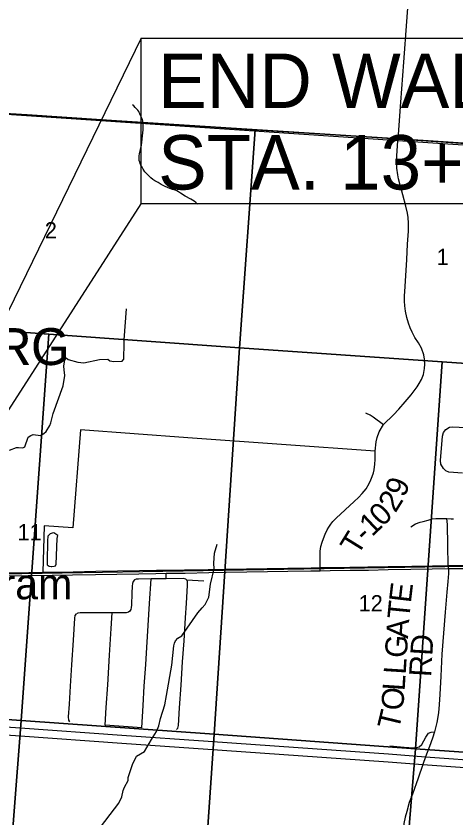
# Model space of a CAD drawing. Extents: x 0 to 34, y 0 to 22.
# Drawn here: x 3.646 to 4.778, y 16.59 to 18.654 of the extents above; entities that cross this region are included whole.
import ezdxf

# ---------------------------------------------------------------- set-up
doc = ezdxf.new("R2010")
doc.units = 0
for name, color, linetype in [('GM_X_City_Street', 7, 'Continuous'), ('GM_X_Corporation', 7, 'Continuous'), ('GM_X_Corporation_Text', 7, 'Continuous'), ('GM_X_Interstate_Route', 7, 'Continuous'), ('GM_X_Minor_Lake', 7, 'Continuous'), ('GM_X_Minor_River', 7, 'Continuous'), ('GM_X_Rail_Line', 7, 'Continuous'), ('GM_X_Section', 7, 'Continuous'), ('GM_X_Section_Text', 7, 'Continuous'), ('GM_X_Township_Road', 7, 'Continuous'), ('GM_X_Township_Road_Text', 7, 'Continuous'), ('GM_X_Unincorporated_Text', 7, 'Continuous'), ('GM_X_US_Route', 7, 'Continuous'), ('SH_Text', 7, 'Continuous')]:
    doc.layers.add(name, color=color, linetype=linetype)

msp = doc.modelspace()

# ---------------------------------------------------------------- linework, layer by layer
at = {"layer": 'GM_X_City_Street'}
for points in [[(3.4177, 18.4149), (4.6284, 18.3336), (5.2084, 18.2946), (5.2627, 18.2891), (5.912, 18.251), (6.0938, 18.2359), (6.2605, 18.224), (6.3251, 19.3282)], [(4.113, 18.1698), (4.1088, 18.1735), (4.1041, 18.1771), (4.0958, 18.1823), (4.0812, 18.1905), (4.0693, 18.1977), (4.0641, 18.2013), (4.0598, 18.2038), (4.0552, 18.2057), (4.049, 18.2077), (4.0417, 18.2102), (4.0299, 18.2154), (4.0196, 18.2205), (4.0115, 18.2252), (4.0036, 18.2298), (3.9982, 18.2332), (3.9929, 18.2372), (3.9884, 18.2413), (3.9831, 18.2467), (3.9776, 18.2531), (3.973, 18.2599), (3.9694, 18.2662), (3.9673, 18.2703), (3.9656, 18.2745), (3.9645, 18.278), (3.9632, 18.2821), (3.9627, 18.2868), (3.9627, 18.2902), (3.9629, 18.2936), (3.9635, 18.2989), (3.9686, 18.3216), (3.9728, 18.3528), (3.9733, 18.3609), (3.9736, 18.3673), (3.9735, 18.3729), (3.973, 18.3777), (3.9723, 18.3835), (3.9712, 18.3878), (3.9691, 18.393), (3.9667, 18.3978), (3.9647, 18.4021), (3.963, 18.4058), (3.9617, 18.4084), (3.9594, 18.4115), (3.9565, 18.4147), (3.9527, 18.4184), (3.9488, 18.4223), (3.9462, 18.4254)]]:
    msp.add_lwpolyline(points, dxfattribs=at)
at = {"layer": 'GM_X_Corporation'}
for points in [[(3.4218, 18.4152), (4.6285, 18.3373), (5.2113, 18.299), (5.2682, 18.2953), (5.912, 18.251), (6.0938, 18.2359), (6.2646, 18.2231), (6.3253, 19.1073), (6.3374, 19.2897), (6.3556, 19.5188), (6.3621, 19.6044), (6.385, 20.0884), (6.3883, 20.1254), (6.389, 20.1539), (6.3927, 20.2003), (6.4001, 20.2844), (6.4016, 20.3608), (6.4097, 20.4361), (6.4277, 20.7531), (6.4325, 20.8009), (6.4385, 20.9), (2.1, 20.9)], [(7.0679, 18.1923), (6.7672, 18.2007), (6.2646, 18.2231), (6.0938, 18.2359), (5.912, 18.251), (5.2682, 18.2953), (5.2113, 18.299), (4.6285, 18.3373), (3.4218, 18.4152)]]:
    msp.add_lwpolyline(points, dxfattribs=at)
at = {"layer": 'GM_X_Interstate_Route'}
for points in [[(3.3501, 16.8435), (3.6568, 16.822), (3.9185, 16.8032), (4.14, 16.7877), (4.3722, 16.7712), (4.604, 16.7548), (4.6996, 16.7473), (4.8669, 16.7351), (5.1594, 16.714), (5.3993, 16.6976), (5.5708, 16.6871), (5.7197, 16.6768), (5.8676, 16.668), (5.8733, 16.6677), (6.0223, 16.6571), (6.2793, 16.6405), (6.5008, 16.6267), (6.5803, 16.6216)], [(3.3497, 16.8226), (3.6565, 16.8011), (3.9181, 16.7823), (4.1396, 16.7667), (4.3718, 16.7503), (4.6036, 16.7339), (4.693, 16.7276), (4.8604, 16.7157), (5.1529, 16.6946), (5.3928, 16.6782), (5.5644, 16.6677), (5.7091, 16.6577), (5.7188, 16.6572), (5.8539, 16.6483)]]:
    msp.add_lwpolyline(points, dxfattribs=at)
at = {"layer": 'GM_X_Minor_Lake'}
for points in [[(3.7517, 17.3091), (3.754, 17.3167), (3.7437, 17.3236), (3.7388, 17.3232), (3.7343, 17.3213), (3.7282, 17.3153), (3.727, 17.3035), (3.727, 17.283), (3.7262, 17.2697), (3.7265, 17.2409)], [(3.7265, 17.2409), (3.7318, 17.2378), (3.7368, 17.2367), (3.7383, 17.2367), (3.744, 17.2382), (3.7477, 17.2389), (3.7493, 17.2431), (3.7517, 17.3091)]]:
    msp.add_lwpolyline(points, dxfattribs=at)
at = {"layer": 'GM_X_Minor_River'}
for points in [[(3.7181, 17.5795), (3.7235, 17.5844), (3.7329, 17.5996), (3.7356, 17.6068), (3.7421, 17.631), (3.7676, 17.7023), (3.7715, 17.7289), (3.7704, 17.7433), (3.7696, 17.7524), (3.7719, 17.7688), (3.775, 17.7737), (3.7806, 17.7695), (3.8048, 17.7626), (3.8208, 17.7614), (3.8609, 17.7697), (3.8825, 17.7708), (3.8874, 17.7662), (3.8976, 17.7643), (3.9188, 17.7654), (3.9234, 17.7707), (3.9242, 17.8121), (3.9246, 17.8208), (3.9301, 17.9005)], [(3.6298, 17.5368), (3.6473, 17.5432), (3.6522, 17.5432), (3.6635, 17.5428), (3.6692, 17.545), (3.6772, 17.5697), (3.684, 17.5746), (3.6905, 17.5765), (3.7094, 17.5746), (3.7181, 17.5795)], [(3.852, 16.5519), (3.9105, 16.6281), (3.9181, 16.6444), (3.9219, 16.6604), (3.9249, 16.6695), (3.9344, 16.6865), (3.9348, 16.6937), (3.9455, 16.7271), (3.9561, 16.7487), (3.977, 16.7612), (3.9949, 16.7919), (4.0074, 16.812), (4.0139, 16.8268), (4.0177, 16.8458), (4.0287, 16.8814), (4.033, 16.9046), (4.0468, 16.9835), (4.0518, 17.0329), (4.0537, 17.0401), (4.0563, 17.0461), (4.0628, 17.0526), (4.073, 17.059), (4.1137, 17.1178), (4.1254, 17.131), (4.1323, 17.1393), (4.1425, 17.1579), (4.146, 17.1917), (4.1556, 17.2312), (4.1548, 17.2452), (4.1564, 17.2714), (4.1636, 17.2949)]]:
    msp.add_lwpolyline(points, dxfattribs=at)
at = {"layer": 'GM_X_Rail_Line'}
msp.add_lwpolyline([(2.1, 17.1885), (2.293, 17.1932), (3.2433, 17.211), (3.5049, 17.2168), (5.1641, 17.2441), (5.3961, 17.2441), (6.3843, 17.2591), (6.7484, 17.272), (7.243, 17.2836), (8.0477, 17.3015), (8.4974, 17.3184), (8.9, 17.3324)], dxfattribs=at)
at = {"layer": 'GM_X_Section'}
for points in [[(3.2487, 18.4259), (3.6748, 18.4), (4.2612, 18.3613), (4.2214, 17.7996), (3.7302, 17.8352), (3.2112, 17.8728)], [(4.2612, 18.3613), (4.4567, 18.3488), (4.4602, 18.3486), (4.9805, 18.3133), (5.2662, 18.2926), (5.2271, 17.7305), (4.7425, 17.7636), (4.2214, 17.7996)], [(3.2112, 17.8728), (3.7302, 17.8352), (3.6598, 16.8406), (3.1425, 16.8774)], [(3.7302, 17.8352), (4.2214, 17.7996), (4.1558, 16.8052), (3.6598, 16.8406)], [(4.2214, 17.7996), (4.7425, 17.7636), (4.6741, 16.7675), (4.1558, 16.8052)], [(4.7425, 17.7636), (5.2271, 17.7305), (5.1577, 16.7346), (4.6741, 16.7675)], [(3.1425, 16.8774), (3.6598, 16.8406), (3.5815, 15.8402), (3.0715, 15.8772)], [(3.6598, 16.8406), (4.1558, 16.8052), (4.0871, 15.8035), (3.5815, 15.8402)], [(4.1558, 16.8052), (4.6741, 16.7675), (4.5921, 15.7668), (4.0871, 15.8035)], [(4.6741, 16.7675), (5.1577, 16.7346), (5.0919, 15.7328), (4.5921, 15.7668)]]:
    msp.add_lwpolyline(points, close=True, dxfattribs=at)
at = {"layer": 'GM_X_Township_Road'}
for p, q in [((4.032, 17.2052), (4.0323, 17.2195)), ((3.9695, 16.8216), (3.8753, 16.8284))]:
    msp.add_line(p, q, dxfattribs=at)
for points in [[(4.6288, 18.3368), (4.6358, 18.4323), (4.6439, 18.5348), (4.6588, 18.7455)], [(5.2116, 18.2984), (4.6288, 18.3368), (3.4221, 18.4146)], [(4.4287, 17.2262), (4.4287, 17.2342), (4.4285, 17.253), (4.4283, 17.2763), (4.4306, 17.2888), (4.4339, 17.2996), (4.4369, 17.3095), (4.4413, 17.3205), (4.4464, 17.3317), (4.4505, 17.3386), (4.4556, 17.3458), (4.4612, 17.3527), (4.4696, 17.3613), (4.5156, 17.404), (4.5273, 17.415), (4.5368, 17.4247), (4.5467, 17.4367), (4.5544, 17.4507), (4.5592, 17.4602), (4.5626, 17.4686), (4.5656, 17.4778), (4.5672, 17.4862), (4.5694, 17.5005), (4.5702, 17.5122), (4.57, 17.5339), (4.5727, 17.5576), (4.5751, 17.569), (4.5806, 17.5836), (4.5918, 17.6024), (4.6175, 17.6277), (4.6312, 17.642), (4.6473, 17.6608), (4.6625, 17.679), (4.678, 17.6995), (4.6833, 17.7079), (4.6892, 17.7187), (4.6939, 17.7308), (4.6969, 17.7463), (4.6975, 17.758), (4.6968, 17.7709), (4.695, 17.7814), (4.6894, 17.7986), (4.6814, 17.8126), (4.6721, 17.8267), (4.6648, 17.8402), (4.6599, 17.8517), (4.6556, 17.8637), (4.6514, 17.8775), (4.6477, 17.8946), (4.6461, 17.9082), (4.6451, 17.9196), (4.6452, 17.9331), (4.6468, 17.9579), (4.6512, 18.0268), (4.6535, 18.0667), (4.6559, 18.1002), (4.6561, 18.1087), (4.6559, 18.1206), (4.6547, 18.1351), (4.6529, 18.1467), (4.6489, 18.1648), (4.6411, 18.1935), (4.6347, 18.2181), (4.6303, 18.2349), (4.6281, 18.2454), (4.626, 18.2619), (4.6253, 18.2758), (4.6254, 18.2867), (4.6259, 18.2939), (4.6286, 18.333), (4.6288, 18.3368)], [(4.5447, 17.6324), (4.5504, 17.6302), (4.5573, 17.6272), (4.5652, 17.6224), (4.5918, 17.6024)], [(4.57, 17.5339), (4.0877, 17.5682), (3.8122, 17.5889), (3.7926, 17.3369), (3.7189, 17.3421), (3.7153, 17.2223)], [(4.7949, 17.477), (4.7596, 17.4797), (4.7519, 17.4829), (4.7456, 17.4889), (4.7389, 17.5008), (4.7382, 17.5099), (4.7432, 17.5727), (4.746, 17.5819), (4.7519, 17.59), (4.7614, 17.5957), (4.7688, 17.5964), (4.8035, 17.5944)], [(4.6617, 17.3394), (4.6737, 17.3465), (4.686, 17.3509), (4.6934, 17.3528), (4.7065, 17.3566), (4.7166, 17.3596), (4.7256, 17.361), (4.7357, 17.361), (4.7453, 17.3607), (4.7546, 17.361), (4.7655, 17.3596), (4.7718, 17.3593)], [(4.7589, 17.2316), (4.7579, 17.2393), (4.7567, 17.2907), (4.7556, 17.3451), (4.7546, 17.361)], [(4.7589, 17.2316), (4.7585, 17.2187), (4.7571, 17.1987), (4.7546, 17.1709), (4.7504, 17.1193), (4.7416, 17.011), (4.7393, 16.9545), (4.7365, 16.9075)], [(4.1289, 17.1995), (4.0855, 17.2018), (4.0831, 17.2046), (4.0797, 17.2057), (4.076, 17.206), (4.032, 17.2052), (3.9941, 17.2049), (3.9611, 17.2048), (3.9551, 17.2042), (3.9511, 17.2025), (3.9477, 17.1987), (3.9458, 17.1932), (3.9449, 17.1868), (3.9441, 17.1687), (3.943, 17.1377), (3.9425, 17.1312), (3.9414, 17.1267), (3.9391, 17.1222), (3.9354, 17.1192), (3.9292, 17.1176), (3.9194, 17.1176), (3.8931, 17.118), (3.8112, 17.1181), (3.8053, 17.1169), (3.8014, 17.1149)], [(3.9695, 16.8216), (3.9733, 16.8797), (3.976, 16.9292), (3.9798, 16.9844), (3.9826, 17.0286), (3.9859, 17.0848), (3.9897, 17.1417), (3.9941, 17.2049)], [(4.059, 16.8171), (4.0626, 16.8212), (4.0645, 16.8277), (4.0671, 16.8736), (4.0708, 16.9314), (4.0748, 16.992), (4.0785, 17.0453), (4.0824, 17.1053), (4.0845, 17.143), (4.0874, 17.1884), (4.0872, 17.198), (4.0855, 17.2018)], [(3.7849, 16.8372), (3.782, 16.8415), (3.7815, 16.8505), (3.7838, 16.8826), (3.7867, 16.9288), (3.7899, 16.9839), (3.7938, 17.0477), (3.7975, 17.104), (3.7987, 17.1105), (3.8014, 17.1149)], [(3.8753, 16.8284), (3.878, 16.8743), (3.882, 16.9324), (3.8865, 17.0087), (3.8911, 17.0774), (3.8931, 17.118)], [(4.7365, 16.9075), (4.7349, 16.8816), (4.7327, 16.8601), (4.7287, 16.8354), (4.7226, 16.8114), (4.7174, 16.7948), (4.7099, 16.7734), (4.6996, 16.7473), (4.693, 16.7276), (4.6809, 16.6925), (4.666, 16.6508), (4.6578, 16.63), (4.6511, 16.6064), (4.6473, 16.5916), (4.6436, 16.576), (4.6429, 16.5638), (4.6368, 16.5019), (4.6366, 16.4999)], [(4.6073, 16.7755), (4.6447, 16.7723), (4.669, 16.7705), (4.6775, 16.7709), (4.683, 16.7731), (4.6897, 16.7787), (4.7001, 16.798), (4.7071, 16.8079), (4.7136, 16.811), (4.7226, 16.8114)]]:
    msp.add_lwpolyline(points, dxfattribs=at)
at = {"layer": 'GM_X_US_Route'}
for points in [[(3.6263, 17.221), (3.6789, 17.2218), (3.7153, 17.2223), (3.7397, 17.2227), (3.7932, 17.2237), (3.8519, 17.2247), (3.9069, 17.2255), (3.9639, 17.2267), (4.0072, 17.2273), (4.0339, 17.2276), (4.0795, 17.2283), (4.14, 17.2294), (4.1861, 17.2301), (4.239, 17.2308), (4.2922, 17.2317), (4.3455, 17.2326), (4.4053, 17.2336), (4.4287, 17.2342), (4.4523, 17.2345), (4.5051, 17.2353), (4.5511, 17.2361), (4.6034, 17.237), (4.664, 17.2379), (4.7173, 17.2388), (4.7579, 17.2393), (4.8008, 17.2401)], [(4.7589, 17.2316), (4.8003, 17.232), (4.8608, 17.2331), (4.9138, 17.2338), (4.9699, 17.2346), (5.0275, 17.2355), (5.0431, 17.2358)], [(3.6247, 17.2129), (3.6773, 17.2137), (3.7388, 17.2148), (3.7916, 17.2156), (3.8504, 17.2166), (3.9056, 17.2176), (3.9623, 17.2185), (4.0056, 17.2192), (4.0323, 17.2195), (4.0811, 17.2203), (4.1418, 17.2215), (4.1871, 17.2222), (4.2399, 17.2229), (4.2928, 17.2238), (4.3454, 17.2246), (4.4048, 17.2257), (4.4287, 17.2262), (4.4539, 17.2265), (4.5053, 17.2273), (4.5529, 17.228), (4.6036, 17.2289), (4.6619, 17.2299), (4.7165, 17.2307), (4.7589, 17.2316)]]:
    msp.add_lwpolyline(points, dxfattribs=at)
at = {"layer": 'SH_Text'}
for points in [[(3.1124, 16.8393), (3.9683, 18.1701), (3.9683, 18.5968)], [(3.9683, 18.5968), (5.2868, 18.5968), (5.2868, 18.1701), (3.9683, 18.1701)]]:
    msp.add_lwpolyline(points, close=True, dxfattribs=at)

# ---------------------------------------------------------------- texts
at = {"layer": 'GM_X_Corporation_Text'}
for p in [(2.7208, 17.7555), (2.722, 17.7558)]:
    msp.add_text('REYNOLDSBURG', height=0.094697, rotation=0, dxfattribs=at).set_placement(p)
at = {"layer": 'GM_X_Section_Text'}
for s, height, p in [('2', 0.0419, (3.7203, 18.0814)), ('1', 0.0419, (4.7278, 18.0128)), ('11', 0.04186, (3.6499, 17.3044)), ('12', 0.04186, (4.5274, 17.1214))]:
    msp.add_text(s, height=height, rotation=0, dxfattribs=at).set_placement(p)
at = {"layer": 'GM_X_Township_Road_Text'}
for s, height, rotation, p in [('9', 0.0568, 68.2795, (4.6456, 17.4129)), ('2', 0.0568, 58.0091, (4.6221, 17.3733)), ('0', 0.0568, 45.0771, (4.5887, 17.3376)), ('1', 0.0568, 43.3027, (4.5618, 17.3123)), ('T', 0.0568, 58.2858, (4.525, 17.2631)), ('-', 0.0568, 43.2777, (4.5448, 17.2962)), ('E', 0.0568, 83.2561, (4.6617, 17.1418)), ('T', 0.0568, 84.4284, (4.6576, 17.0998)), ('A', 0.0568, 86.2453, (4.6544, 17.0504)), ('G', 0.0568, 86.2467, (4.6511, 17.0005)), ('RD', 0.05682, 86.5467, (4.7136, 16.9518)), ('L', 0.0568, 86.2475, (4.6483, 16.9581)), ('L', 0.0568, 86.2526, (4.6456, 16.9157)), ('O', 0.0568, 85.6534, (4.6417, 16.8652)), ('T', 0.0568, 76.5084, (4.6303, 16.814))]:
    msp.add_text(s, height=height, rotation=rotation, dxfattribs=at).set_placement(p)
at = {"layer": 'GM_X_Unincorporated_Text'}
msp.add_text('Wagram', height=0.07898, rotation=0, dxfattribs=at).set_placement((3.3919, 17.1527))
at = {"layer": 'SH_Text'}
for s, p in [('END WALL      ', (4.0118, 18.4173)), ('STA. 13+48     ', (4.0118, 18.2073))]:
    msp.add_text(s, height=0.14, dxfattribs=at).set_placement(p)

doc.saveas('drawing.dxf')
